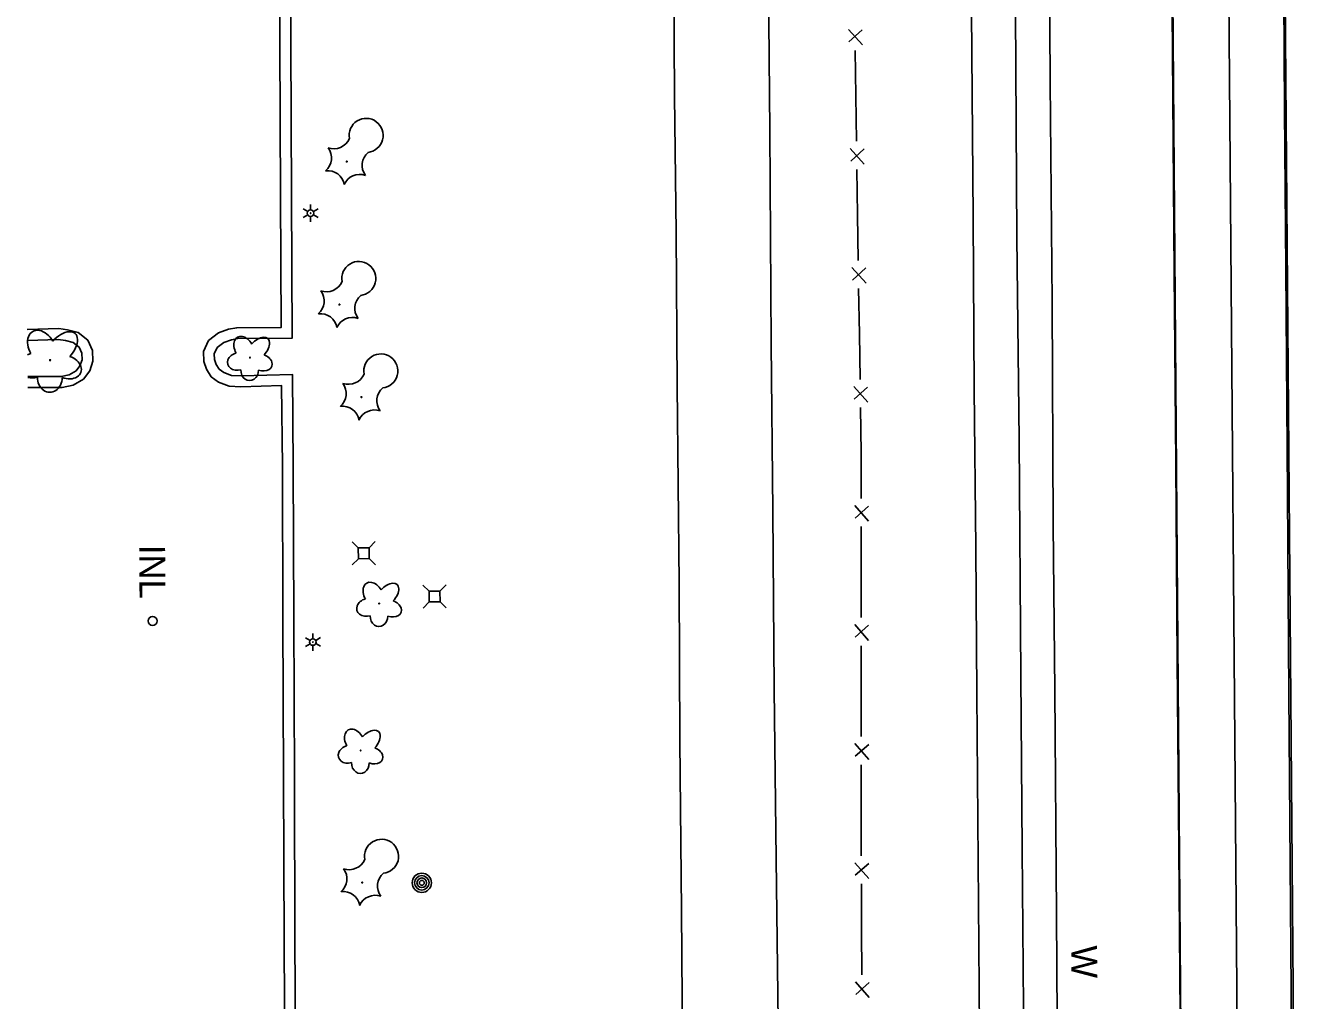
# Model space of a CAD drawing. Extents: x 588843 to 2552415, y 180129 to 269402.
# Drawn here: x 593752.2 to 594050.2, y 180940.3 to 181165.4 of the extents above; entities that cross this region are included whole.
import ezdxf

# ---------------------------------------------------------------- set-up
doc = ezdxf.new("R2010")
doc.units = 0
for name, color, linetype in [('Default', 7, 'Continuous'), ('E_DRN', 7, 'Continuous'), ('E_DRN_Text', 7, 'Continuous'), ('E_DWY', 7, 'Continuous'), ('E_FEN_P', 7, 'Continuous'), ('E_LAND_Vegetation', 7, 'Continuous'), ('E_LTG', 7, 'Continuous'), ('E_MISCPROP', 7, 'Continuous'), ('E_RDWY', 7, 'Continuous'), ('E_RDWY_Gravel', 7, 'Continuous'), ('E_UTL_AG_Bold', 7, 'Continuous'), ('E_WAL', 7, 'Continuous'), ('E_WAL_Text', 7, 'Continuous'), ('P_RDWY_PavtEdge', 7, 'Continuous'), ('P_TC_BarrierConc', 7, 'Continuous')]:
    doc.layers.add(name, color=color, linetype=linetype)

# ---------------------------------------------------------------- blocks, each defined once
blk = doc.blocks.new('W_3')
at = {"layer": 'E_WAL_Text'}
blk.add_text('W', height=12, dxfattribs=at).set_placement((-4.46, -6))
blk = doc.blocks.new('INLT_3')
at = {"layer": 'E_DRN_Text'}
blk.add_text('INL', height=12, dxfattribs=at).set_placement((-11.03, -6))
blk = doc.blocks.new('PED')
at = {"layer": 'Default'}
for p, q in [((-2.5, 2.5), (-5.33, 5.33)), ((2.5, 2.5), (5.33, 5.33)), ((-2.5, -2.5), (-5.33, -5.33)), ((2.5, -2.5), (5.33, -5.33))]:
    blk.add_line(p, q, dxfattribs=at)
blk.add_lwpolyline([(-2.5, -2.5), (2.5, -2.5), (2.5, 2.5), (-2.5, 2.5)], close=True, dxfattribs=at)
blk = doc.blocks.new('LPOL')
at = {"layer": 'Default'}
for p, q in [((-4, 0), (-1.5, 0)), ((-0.75, 1.3), (-2, 3.46)), ((0.75, 1.3), (2, 3.46)), ((1.5, 0), (4, 0)), ((-2, -3.46), (-0.75, -1.3)), ((2, -3.46), (0.75, -1.3))]:
    blk.add_line(p, q, dxfattribs=at)
for radius in [1.5, 1.5, 1.5, 0.125]:
    blk.add_circle((0, 0), radius, dxfattribs=at)
blk = doc.blocks.new('POLE')
at = {"layer": 'Default'}
for radius in [4.46, 3.35, 2.23, 1.12]:
    blk.add_circle((0, 0), radius, dxfattribs=at)
blk = doc.blocks.new('CTRE')
at = {"layer": 'Default'}
blk.add_circle((0, 0), 0.223, dxfattribs=at)
for centre, start, end in [((-11.97, 8.96), 280.2067, 5.97162), ((1.81, 14.92), 220.21132, 305.97623), ((13.83, 5.89), 160.21133, 245.97624), ((-13.83, -5.9), 340.21132, 65.97623), ((12.03, -9.04), 185.92721, 100.25111), ((-1.81, -14.93), 40.21133, 125.97624)]:
    blk.add_arc(centre, 7.87, start, end, dxfattribs=at)
blk = doc.blocks.new('DTRE')
at = {"layer": 'Default'}
blk.add_circle((-0.18, 0), 0.183, dxfattribs=at)
for centre, major_axis, ratio in [((-1.87, 5.32), (1.36, -4.98), 0.782863), ((4.06, 2.74), (-5.27, -2.93), 0.691916), ((-5.87, 0.15), (4.93, -0.12), 0.832022), ((-2.49, -5.24), (1.8, 4.86), 0.716896), ((3.54, -3.71), (-5.01, 4.58), 0.560249)]:
    blk.add_ellipse(centre, major_axis=major_axis, ratio=ratio, start_param=1.570796, end_param=4.712389, dxfattribs=at)

msp = doc.modelspace()

# ---------------------------------------------------------------- linework, layer by layer
at = {"layer": 'E_DRN'}
msp.add_circle((593781.47, 181027.91), 1.04, dxfattribs=at)
at = {"layer": 'E_DWY'}
for points in [[(593810.71, 181224.63), (593810.79, 181182.72), (593810.87, 181161.35)], [(593813.21, 181224.64), (593813.29, 181182.72), (593813.37, 181161.36)], [(593811.46, 181063.67), (593811.28, 181082.3), (593801.88, 181082), (593799.2, 181082.18), (593796.74, 181083.07), (593795.04, 181084.34), (593793.91, 181086.07), (593793.29, 181087.88), (593793.22, 181090.17), (593794.39, 181092.68), (593796.67, 181094.49), (593799.03, 181095.31), (593800.91, 181095.66), (593811.2, 181095.72), (593811.04, 181126.11), (593810.87, 181161.35)], [(593813.96, 181063.69), (593813.76, 181084.88), (593801.93, 181084.5), (593799.72, 181084.65), (593797.94, 181085.3), (593796.89, 181086.08), (593796.17, 181087.18), (593795.78, 181088.33), (593795.74, 181089.65), (593796.41, 181091.08), (593797.9, 181092.27), (593799.67, 181092.89), (593801.15, 181093.16), (593813.71, 181093.23), (593813.54, 181126.12), (593813.37, 181161.36)], [(593752.66, 181081.87), (593760.61, 181081.87), (593763.15, 181082.39), (593765.52, 181083.76), (593766.97, 181085.69), (593767.7, 181087.9), (593767.64, 181090.4), (593766.5, 181092.75), (593764.31, 181094.53), (593761.83, 181095.17), (593759.84, 181095.45), (593752.55, 181095.23)], [(593752.64, 181084.37), (593760.36, 181084.37), (593762.25, 181084.75), (593763.82, 181085.67), (593764.72, 181086.86), (593765.19, 181088.27), (593765.15, 181089.8), (593764.5, 181091.16), (593763.16, 181092.24), (593761.34, 181092.71), (593759.7, 181092.94), (593752.57, 181092.73)], [(593812.69, 180798.25), (593812.52, 180837.05), (593812.26, 180881.68), (593812.2, 180911.3), (593802.73, 180911.23), (593800.09, 180911.47), (593797.59, 180912.12), (593795.76, 180913.49), (593794.45, 180915.53), (593793.99, 180918.02), (593794.41, 180920.81), (593796.04, 180922.84), (593798.26, 180924.17), (593800.29, 180924.62), (593801.94, 180924.8), (593812.04, 180924.84), (593811.86, 180953.69), (593811.74, 180991.64), (593811.57, 181028.59), (593811.46, 181063.69)], [(593815.19, 180798.26), (593815.02, 180837.07), (593814.76, 180881.69), (593814.69, 180913.81), (593802.84, 180913.73), (593800.52, 180913.94), (593798.7, 180914.41), (593797.62, 180915.22), (593796.82, 180916.47), (593796.52, 180918.06), (593796.78, 180919.77), (593797.71, 180920.93), (593799.2, 180921.82), (593800.7, 180922.15), (593802.09, 180922.3), (593814.56, 180922.35), (593814.36, 180953.71), (593814.24, 180991.65), (593814.07, 181028.6), (593813.96, 181063.69)]]:
    msp.add_lwpolyline(points, dxfattribs=at)
at = {"layer": 'E_FEN_P'}
for p, q in [((593942.16, 181164.58), (593945.4, 181160.97)), ((593945.34, 181164.46), (593942.26, 181161.66)), ((593942.57, 181137.08), (593945.81, 181133.47)), ((593945.76, 181136.96), (593942.68, 181134.16)), ((593942.98, 181109.58), (593946.22, 181105.97)), ((593946.17, 181109.46), (593943.09, 181106.66)), ((593943.39, 181082.07), (593946.63, 181078.46)), ((593946.58, 181081.95), (593943.5, 181079.16)), ((593943.64, 181054.59), (593946.82, 181050.94)), ((593946.82, 181054.43), (593943.7, 181051.67)), ((593943.65, 181027.09), (593946.83, 181023.43)), ((593946.83, 181026.92), (593943.71, 181024.17)), ((593943.66, 180999.58), (593946.85, 180995.92)), ((593946.84, 180999.41), (593943.73, 180996.66)), ((593943.67, 180972.07), (593946.86, 180968.42)), ((593946.86, 180971.91), (593943.74, 180969.16)), ((593943.76, 180944.56), (593946.96, 180940.92)), ((593946.94, 180944.41), (593943.84, 180941.65))]:
    msp.add_line(p, q, dxfattribs=at)
for points in [[(593943.7, 181159.72), (593943.86, 181149.22)], [(593943.86, 181149.22), (593944.01, 181138.72)], [(593944.11, 181132.22), (593944.27, 181121.72)], [(593944.27, 181121.72), (593944.43, 181111.21)], [(593944.52, 181104.71), (593944.68, 181094.21)], [(593944.68, 181094.21), (593944.84, 181083.71)], [(593944.94, 181077.21), (593945.09, 181066.71)], [(593945.09, 181066.71), (593945.1, 181066.15), (593945.11, 181056.21)], [(593945.11, 181049.71), (593945.11, 181039.21)], [(593945.11, 181039.21), (593945.12, 181028.7)], [(593945.12, 181022.2), (593945.13, 181011.7)], [(593945.13, 181011.7), (593945.13, 181001.2)], [(593945.13, 180994.7), (593945.14, 180984.19)], [(593945.14, 180984.19), (593945.14, 180973.69)], [(593945.15, 180967.19), (593945.19, 180956.69)], [(593945.19, 180956.69), (593945.22, 180946.19)]]:
    msp.add_lwpolyline(points, dxfattribs=at)
at = {"layer": 'E_LAND_Vegetation'}
msp.add_circle((593757.84, 181088.16), 0.128, dxfattribs=at)
for centre, major_axis, ratio, start_param, end_param in [((593755.9, 181091.11), (2.08, -3.67), 0.691916, 1.570796, 4.712389), ((593760.41, 181090.79), (-3.18, -3.53), 0.560249, 1.570796, 4.712389), ((593754.12, 181086.95), (3.48, 0.98), 0.782863, 1.570796, 1.794819), ((593761.52, 181086.57), (-3.41, 1.23), 0.716896, 1.570796, 4.712389), ((593754.12, 181086.95), (3.48, 0.98), 0.782863, 4.068442, 4.712389), ((593757.76, 181084.18), (0.06, 3.45), 0.832022, 1.570796, 4.712389)]:
    msp.add_ellipse(centre, major_axis=major_axis, ratio=ratio, start_param=start_param, end_param=end_param, dxfattribs=at)
at = {"layer": 'E_RDWY'}
for points in [[(593907.17, 180543.98), (593906.94, 180581.8), (593906.68, 180617.44), (593906.38, 180657.53), (593906.05, 180697.51), (593905.29, 180731.59), (593904.83, 180770.62), (593904.54, 180810.93), (593904.31, 180853.03), (593904.12, 180892.61), (593903.81, 180930.07), (593903.6, 180961.11), (593903.25, 181000.18), (593903.04, 181036.62), (593902.61, 181082.22), (593902.42, 181117.68), (593901.99, 181149.13), (593901.88, 181174.73)], [(593923.73, 181174.95), (593924.05, 181141.24), (593924.35, 181091.92), (593924.71, 181053.29), (593924.99, 181012.18), (593925.48, 180972.85), (593925.93, 180935.38), (593926.35, 180896.28), (593926.53, 180858.01), (593926.57, 180820.08), (593926.78, 180784.07), (593926.85, 180743.7), (593927.25, 180705.65), (593927.75, 180671.1), (593928.23, 180633.7), (593928.33, 180601.97), (593928.89, 180545.4)], [(594047.68, 180543.4), (594047.18, 180592.8), (594046.88, 180640.75), (594046.52, 180678.52), (594046.15, 180719.3), (594046.02, 180757.28), (594045.76, 180793.7), (594045.43, 180833.59), (594045.01, 180879.13), (594044.54, 180923.49), (594044.25, 180961.97), (594043.86, 181011.13), (594043.56, 181057.11), (594043.16, 181109.33), (594042.87, 181145.95), (594042.68, 181172.17)], [(593981.97, 181015.32), (593981.57, 181069.65), (593981.06, 181116.55), (593980.74, 181168.67)], [(594016.95, 181169.03), (594017.4, 181108.37), (594017.76, 181064.3), (594018.06, 181018.76), (594018.42, 180975.19), (594018.74, 180936.8), (594018.97, 180896.15), (594019.43, 180852.87), (594019.84, 180808.54), (594020.11, 180765.32), (594020.56, 180721.75), (594021.01, 180674.24), (594021.29, 180627.41), (594021.63, 180584.34), (594021.9, 180542.52)], [(593985.6, 180542.06), (593985.19, 180589.94), (593984.81, 180641.08), (593984.42, 180689.85), (593984.11, 180735.89), (593983.76, 180782.32), (593983.4, 180829.82), (593983.09, 180881.18), (593982.67, 180929.66), (593982.27, 180975.15), (593981.97, 181015.32)]]:
    msp.add_lwpolyline(points, dxfattribs=at)
at = {"layer": 'E_RDWY_Gravel'}
msp.add_lwpolyline([(593975.39, 180542.38), (593975.09, 180581.82), (593974.82, 180627.24), (593974.56, 180660.66), (593974.2, 180701.9), (593973.87, 180744.15), (593973.52, 180784.68), (593973.27, 180818.19), (593973.12, 180856.37), (593972.76, 180892.41), (593972.4, 180933.54), (593972.11, 180972.31), (593971.79, 181011.12), (593971.57, 181044.83), (593971.22, 181081.43), (593970.98, 181121.11), (593970.56, 181168.65)], dxfattribs=at)
at = {"layer": 'E_WAL'}
msp.add_lwpolyline([(593992.23, 180730.86), (593991.91, 180756.16), (593991.71, 180788.82), (593991.56, 180819.79), (593991.27, 180852.18), (593990.87, 180887.4), (593990.46, 180923.97), (593990.19, 180960.09), (593989.86, 181011.84), (593989.42, 181050.09), (593989.18, 181101.54), (593988.72, 181152.4), (593988.62, 181178.23)], dxfattribs=at)
at = {"layer": 'P_RDWY_PavtEdge'}
for p, q in [((594024.17, 180268.93), (594014.69, 181468.89)), ((594050.17, 180269.13), (594040.69, 181469.09))]:
    msp.add_line(p, q, dxfattribs=at)
at = {"layer": 'P_TC_BarrierConc'}
msp.add_line((594037.17, 180269.03), (594027.69, 181468.99), dxfattribs=at)

# ---------------------------------------------------------------- block references
at = {"layer": 'E_DRN_Text', "xscale": 0.49999999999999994, "yscale": 0.49999999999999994, "rotation": -89.5545646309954}
msp.add_blockref('INLT_3', (593781.42, 181039.99), dxfattribs=at)
at = {"layer": 'E_LAND_Vegetation', "xscale": 0.49999999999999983, "yscale": 0.4999999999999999, "rotation": 90.44543536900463}
for name, p in [('CTRE', (593826.32, 181134.03)), ('CTRE', (593824.63, 181100.99)), ('DTRE', (593803.97, 181088.84)), ('CTRE', (593829.72, 181079.62)), ('DTRE', (593833.81, 181032.02)), ('DTRE', (593829.53, 180998.08)), ('CTRE', (593829.88, 180967.49))]:
    msp.add_blockref(name, p, dxfattribs=at)
at = {"layer": 'E_LTG', "xscale": 0.49999999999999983, "yscale": 0.4999999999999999, "rotation": 90.44543536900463}
for p in [(593817.96, 181122.12), (593818.5, 181023.04)]:
    msp.add_blockref('LPOL', p, dxfattribs=at)
at = {"layer": 'E_MISCPROP', "xscale": 0.49999999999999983, "yscale": 0.4999999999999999, "rotation": 90.44543536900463}
msp.add_blockref('POLE', (593843.65, 180967.42), dxfattribs=at)
at = {"layer": 'E_UTL_AG_Bold', "xscale": 0.49999999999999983, "yscale": 0.4999999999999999, "rotation": 90.44543536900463}
for p in [(593830.24, 181043.55), (593846.6, 181033.57)]:
    msp.add_blockref('PED', p, dxfattribs=at)
at = {"layer": 'E_WAL_Text', "xscale": 0.49999999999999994, "yscale": 0.49999999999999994, "rotation": -89.5545646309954}
msp.add_blockref('W_3', (593996.6, 180950.73), dxfattribs=at)

doc.saveas('drawing.dxf')
